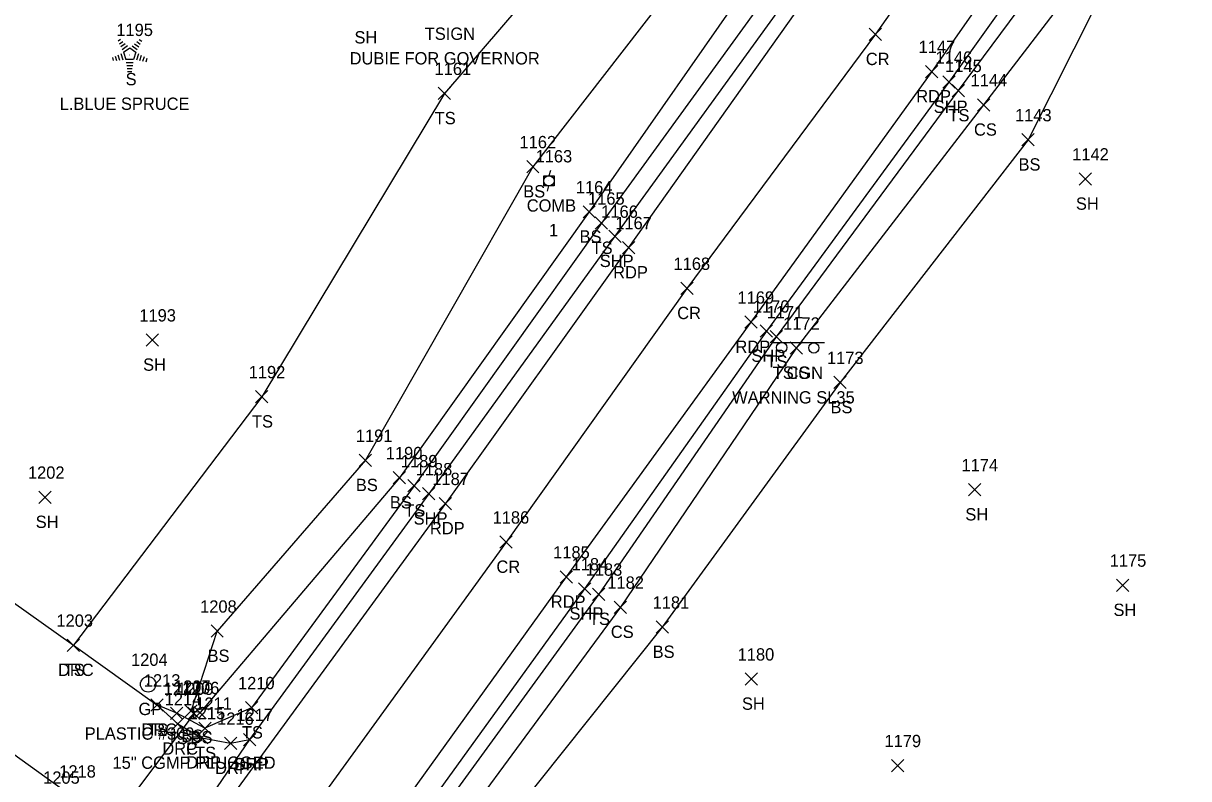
# Model space of a CAD drawing. Extents: x 1520648 to 1523413, y 732854 to 735518.
# Drawn here: x 1522600.4 to 1522789.8, y 734497.2 to 734620 of the extents above; entities that cross this region are included whole.
import ezdxf

# ---------------------------------------------------------------- set-up
doc = ezdxf.new("R2010")
doc.units = 0
for name, color, linetype in [('D_A', 7, 'Continuous'), ('D_C', 7, 'Continuous'), ('D_I', 7, 'Continuous'), ('D_TIC', 7, 'Continuous'), ('DCP', 7, 'Continuous'), ('L_A', 7, 'Continuous'), ('L_C', 7, 'Continuous'), ('L_I', 7, 'Continuous'), ('L_TIC', 7, 'Continuous'), ('LELB', 7, 'Continuous'), ('LTC', 7, 'Continuous'), ('P_A', 7, 'Continuous'), ('P_I', 7, 'Continuous'), ('P_TIC', 7, 'Continuous'), ('PET', 7, 'Continuous'), ('PRC', 7, 'Continuous'), ('PSP', 7, 'Continuous'), ('R_A', 7, 'Continuous'), ('R_C', 7, 'Continuous'), ('R_I', 7, 'Continuous'), ('R_TIC', 7, 'Continuous'), ('RDP', 7, 'Continuous'), ('RGP', 7, 'Continuous'), ('S_A', 7, 'Continuous'), ('S_C', 7, 'Continuous'), ('S_I', 7, 'Continuous'), ('SSGN', 7, 'Continuous'), ('U_A', 7, 'Continuous'), ('U_C', 7, 'Continuous'), ('U_I', 7, 'Continuous'), ('UP', 7, 'Continuous')]:
    doc.layers.add(name, color=color, linetype=linetype)

msp = doc.modelspace()

# ---------------------------------------------------------------- linework, layer by layer
at = {"layer": 'D_TIC'}
for points in [[(1522627.14, 734506.84), (1522629.14, 734508.84)], [(1522629.14, 734506.84), (1522627.14, 734508.84)]]:
    msp.add_lwpolyline(points, dxfattribs=at)
at = {"layer": 'DCP'}
msp.add_lwpolyline([(1522628.14, 734507.84), (1522613.17, 734487.96)], dxfattribs=at)
at = {"layer": 'L_TIC'}
for points in [[(1522667.83, 734607.56), (1522669.83, 734609.56)], [(1522669.83, 734607.56), (1522667.83, 734609.56)], [(1522751.35, 734608.03), (1522753.35, 734610.03)], [(1522753.35, 734608.03), (1522751.35, 734610.03)], [(1522755.48, 734605.7), (1522757.48, 734607.7)], [(1522757.48, 734605.7), (1522755.48, 734607.7)], [(1522762.72, 734600.03), (1522764.72, 734602.03)], [(1522764.72, 734600.03), (1522762.72, 734602.03)], [(1522682.2, 734595.66), (1522684.2, 734597.66)], [(1522684.2, 734595.66), (1522682.2, 734597.66)], [(1522772, 734593.67), (1522774, 734595.67)], [(1522774, 734593.67), (1522772, 734595.67)], [(1522691.36, 734588.33), (1522693.36, 734590.33)], [(1522693.36, 734588.33), (1522691.36, 734590.33)], [(1522693.34, 734586.49), (1522695.34, 734588.49)], [(1522695.34, 734586.49), (1522693.34, 734588.49)], [(1522620.35, 734567.51), (1522622.35, 734569.51)], [(1522622.35, 734567.51), (1522620.35, 734569.51)], [(1522721.77, 734568.04), (1522723.77, 734570.04)], [(1522723.77, 734568.04), (1522721.77, 734570.04)], [(1522725.02, 734566.19), (1522727.02, 734568.19)], [(1522727.02, 734566.19), (1522725.02, 734568.19)], [(1522732.15, 734560.61), (1522734.15, 734562.61)], [(1522734.15, 734560.61), (1522732.15, 734562.61)], [(1522638.13, 734558.29), (1522640.13, 734560.29)], [(1522640.13, 734558.29), (1522638.13, 734560.29)], [(1522654.99, 734547.96), (1522656.99, 734549.96)], [(1522656.99, 734547.96), (1522654.99, 734549.96)], [(1522660.51, 734545.14), (1522662.51, 734547.14)], [(1522662.51, 734545.14), (1522660.51, 734547.14)], [(1522662.89, 734543.83), (1522664.89, 734545.83)], [(1522664.89, 734543.83), (1522662.89, 734545.83)], [(1522754.02, 734543.19), (1522756.02, 734545.19)], [(1522756.02, 734543.19), (1522754.02, 734545.19)], [(1522602.89, 734541.97), (1522604.89, 734543.97)], [(1522604.89, 734541.97), (1522602.89, 734543.97)], [(1522778.1, 734527.67), (1522780.1, 734529.67)], [(1522780.1, 734527.67), (1522778.1, 734529.67)], [(1522692.92, 734526.21), (1522694.92, 734528.21)], [(1522694.92, 734526.21), (1522692.92, 734528.21)], [(1522696.44, 734524.1), (1522698.44, 734526.1)], [(1522698.44, 734524.1), (1522696.44, 734526.1)], [(1522630.88, 734520.21), (1522632.88, 734522.21)], [(1522632.88, 734520.21), (1522630.88, 734522.21)], [(1522630.88, 734520.21), (1522632.88, 734522.21)], [(1522632.88, 734520.21), (1522630.88, 734522.21)], [(1522703.24, 734520.86), (1522705.24, 734522.86)], [(1522705.24, 734520.86), (1522703.24, 734522.86)], [(1522607.52, 734517.92), (1522609.52, 734519.92)], [(1522609.52, 734517.92), (1522607.52, 734519.92)], [(1522717.71, 734512.43), (1522719.71, 734514.43)], [(1522719.71, 734512.43), (1522717.71, 734514.43)], [(1522621.08, 734508.21), (1522623.08, 734510.21)], [(1522623.08, 734508.21), (1522621.08, 734510.21)], [(1522624.31, 734506.86), (1522626.31, 734508.86)], [(1522626.31, 734506.86), (1522624.31, 734508.86)], [(1522626.63, 734507.21), (1522628.63, 734509.21)], [(1522628.63, 734507.21), (1522626.63, 734509.21)], [(1522628.11, 734506.98), (1522630.11, 734508.98)], [(1522630.11, 734506.98), (1522628.11, 734508.98)], [(1522636.49, 734507.77), (1522638.49, 734509.77)], [(1522638.49, 734507.77), (1522636.49, 734509.77)], [(1522628.88, 734504.43), (1522630.88, 734506.43)], [(1522630.88, 734504.43), (1522628.88, 734506.43)], [(1522741.51, 734498.36), (1522743.51, 734500.36)], [(1522743.51, 734498.36), (1522741.51, 734500.36)]]:
    msp.add_lwpolyline(points, dxfattribs=at)
at = {"layer": 'LELB'}
for points in [[(1522855.1, 734830.16), (1522826.24, 734788.65), (1522795.28, 734735.47), (1522774.39, 734704.01), (1522748.32, 734671.46), (1522720.6, 734629.79), (1522692.36, 734589.33), (1522661.51, 734546.14), (1522629.11, 734507.98), (1522627.63, 734508.21), (1522631.88, 734521.21)], [(1522861.38, 734825.29), (1522833.52, 734784.68), (1522798.27, 734733.65), (1522776.55, 734702.76), (1522751.5, 734669.07), (1522723.71, 734627.99), (1522694.34, 734587.49), (1522663.89, 734544.83), (1522637.49, 734508.77), (1522629.88, 734505.43), (1522625.31, 734507.86), (1522622.08, 734509.21)], [(1522751.82, 734797.84), (1522774.11, 734773.6), (1522782.23, 734739.14), (1522764.96, 734707.91), (1522741.94, 734675.96), (1522712.49, 734634.45), (1522683.2, 734596.66), (1522655.99, 734548.96), (1522631.88, 734521.21)], [(1522715.74, 734759.38), (1522736.6, 734748.28), (1522756.98, 734734.14), (1522748.37, 734724.17), (1522727.95, 734685.48), (1522698.99, 734643.64), (1522668.83, 734608.56), (1522639.13, 734559.29), (1522608.52, 734518.92)], [(1522964.59, 734711.8), (1522934.04, 734688.62), (1522903.57, 734670.84), (1522893.31, 734656.71), (1522881.6, 734654.9), (1522856.07, 734664.39), (1522835.94, 734674.96), (1522815.99, 734683.04), (1522809.93, 734682.93), (1522803.99, 734678.79), (1522800.17, 734672.61), (1522781.12, 734647.81), (1522752.35, 734609.03), (1522722.77, 734569.04), (1522693.92, 734527.21), (1522653.61, 734471.8)], [(1522966.98, 734707.81), (1522936.6, 734685.01), (1522907.63, 734664.77), (1522896.44, 734650.45), (1522881.66, 734649.85), (1522854.58, 734659.5), (1522833, 734670.65), (1522815.02, 734680.19), (1522811.05, 734676.42), (1522816.52, 734667.94), (1522809.83, 734658.42), (1522800.06, 734661.2), (1522785.93, 734645.15), (1522763.72, 734601.03), (1522733.15, 734561.61), (1522704.24, 734521.86), (1522660.18, 734466.65)], [(1522785.93, 734645.15), (1522756.48, 734606.7), (1522726.02, 734567.19), (1522697.44, 734525.1), (1522656.53, 734469.54), (1522622.12, 734421.12), (1522590.47, 734378.52), (1522566.34, 734346.2), (1522539.5, 734310.16), (1522511.43, 734266.75), (1522492.81, 734239.83), (1522459.56, 734196.4), (1522434.24, 734163.49), (1522417.99, 734140.69), (1522411.81, 734133.72), (1522406.56, 734130.49), (1522403.25, 734126.38), (1522401.8, 734120.85), (1522386.75, 734098.22)]]:
    msp.add_lwpolyline(points, dxfattribs=at)
at = {"layer": 'LTC'}
for p, q in [((1522615.81, 734617.1), (1522616.16, 734617.36)), ((1522616.02, 734616.63), (1522616.55, 734617.02)), ((1522616.23, 734616.17), (1522616.93, 734616.68)), ((1522616.44, 734615.7), (1522617.32, 734616.34)), ((1522618.47, 734616.64), (1522619.14, 734616.15)), ((1522618.84, 734616.99), (1522619.39, 734616.59)), ((1522619.21, 734617.34), (1522619.63, 734617.04)), ((1522615.3, 734614.6), (1522615.51, 734613.94)), ((1522615.75, 734614.81), (1522616.02, 734613.98)), ((1522616.21, 734615.03), (1522616.54, 734614.01)), ((1522616.66, 734615.25), (1522617.67, 734615.98)), ((1522616.66, 734615.25), (1522617.05, 734614.05)), ((1522617.67, 734615.98), (1522618.67, 734615.26)), ((1522618.09, 734616.3), (1522618.9, 734615.71)), ((1522618.67, 734615.26), (1522618.28, 734614.05)), ((1522619.11, 734614.99), (1522618.77, 734613.95)), ((1522619.55, 734614.74), (1522619.27, 734613.85)), ((1522620, 734614.49), (1522619.76, 734613.76)), ((1522614.84, 734614.38), (1522614.99, 734613.91)), ((1522618.28, 734614.05), (1522617.05, 734614.05)), ((1522618.24, 734613.55), (1522617.1, 734613.55)), ((1522618.16, 734613.05), (1522617.17, 734613.05)), ((1522618.07, 734612.55), (1522617.24, 734612.55)), ((1522620.44, 734614.24), (1522620.26, 734613.66)), ((1522617.99, 734612.05), (1522617.32, 734612.05))]:
    msp.add_line(p, q, dxfattribs=at)
at = {"layer": 'P_TIC'}
for points in [[(1522737.9, 734617.17), (1522739.9, 734619.17)], [(1522739.9, 734617.17), (1522737.9, 734619.17)], [(1522747.04, 734611.12), (1522749.04, 734613.12)], [(1522749.04, 734611.12), (1522747.04, 734613.12)], [(1522749.84, 734609.4), (1522751.84, 734611.4)], [(1522751.84, 734609.4), (1522749.84, 734611.4)], [(1522695.55, 734584.36), (1522697.55, 734586.36)], [(1522697.55, 734584.36), (1522695.55, 734586.36)], [(1522697.77, 734582.51), (1522699.77, 734584.51)], [(1522699.77, 734582.51), (1522697.77, 734584.51)], [(1522707.24, 734575.9), (1522709.24, 734577.9)], [(1522709.24, 734575.9), (1522707.24, 734577.9)], [(1522717.66, 734570.41), (1522719.66, 734572.41)], [(1522719.66, 734570.41), (1522717.66, 734572.41)], [(1522720.18, 734568.96), (1522722.18, 734570.96)], [(1522722.18, 734568.96), (1522720.18, 734570.96)], [(1522665.29, 734542.52), (1522667.29, 734544.52)], [(1522667.29, 734542.52), (1522665.29, 734544.52)], [(1522667.99, 734540.94), (1522669.99, 734542.94)], [(1522669.99, 734540.94), (1522667.99, 734542.94)], [(1522677.84, 734534.68), (1522679.84, 734536.68)], [(1522679.84, 734534.68), (1522677.84, 734536.68)], [(1522687.63, 734529.01), (1522689.63, 734531.01)], [(1522689.63, 734529.01), (1522687.63, 734531.01)], [(1522690.62, 734527.08), (1522692.62, 734529.08)], [(1522692.62, 734527.08), (1522690.62, 734529.08)], [(1522636.15, 734502.6), (1522638.15, 734504.6)], [(1522638.15, 734502.6), (1522636.15, 734504.6)]]:
    msp.add_lwpolyline(points, dxfattribs=at)
at = {"layer": 'PET'}
for points in [[(1522868.59, 734820.36), (1522840.66, 734781.56), (1522808.05, 734736.15), (1522781.8, 734699.35), (1522756.93, 734664.88), (1522728.19, 734624.99), (1522698.77, 734583.51), (1522668.99, 734541.94), (1522630.29, 734488.99), (1522594.44, 734439.3), (1522567.25, 734402.07), (1522538.71, 734362.22), (1522514.31, 734328.64), (1522482.43, 734284.06), (1522464.74, 734260.16), (1522432.63, 734216.53), (1522409.89, 734185.46), (1522384.8, 734151.86)], [(1522887.76, 734807.39), (1522860.85, 734769.52), (1522801.36, 734686.8), (1522776.05, 734652.1), (1522748.04, 734612.12), (1522718.66, 734571.41), (1522688.63, 734530.01), (1522649.15, 734475.23), (1522613.31, 734425.7), (1522584.29, 734385.79), (1522558.85, 734350.63), (1522533.2, 734315.44), (1522501.29, 734271.61), (1522483.1, 734246.38), (1522451.17, 734203.52), (1522426.47, 734169.3), (1522405.75, 734141.77), (1522378.63, 734104.64)]]:
    msp.add_lwpolyline(points, dxfattribs=at)
at = {"layer": 'PRC'}
msp.add_lwpolyline([(1522878.51, 734813.79), (1522851.06, 734774.87), (1522817.97, 734729.86), (1522791.97, 734693.14), (1522766.66, 734657.61), (1522738.9, 734618.17), (1522708.24, 734576.9), (1522678.84, 734535.68), (1522640.14, 734482.21), (1522604.52, 734432.45), (1522576.44, 734394.44), (1522548.3, 734356.14), (1522523.72, 734322.36), (1522491.79, 734277.99), (1522474.03, 734253.33), (1522442.17, 734210.31), (1522417.88, 734177.66), (1522396.73, 734148.57), (1522369.92, 734111.45)], dxfattribs=at)
at = {"layer": 'PSP'}
for points in [[(1522864.28, 734823.23), (1522837.44, 734783.06), (1522805.48, 734737.59), (1522779.45, 734700.71), (1522754.96, 734666.26), (1522726.27, 734626.48), (1522696.55, 734585.36), (1522666.29, 734543.52), (1522637.15, 734503.6), (1522619.94, 734478.45), (1522592.3, 734440.3), (1522565.28, 734403.71), (1522536.3, 734363.73), (1522513.91, 734332.75), (1522468.75, 734270.57), (1522462.45, 734261.84), (1522430.53, 734218.51), (1522407.44, 734186.96), (1522382.7, 734153.4)], [(1522891.61, 734804.38), (1522863.83, 734767.51), (1522842.38, 734738.09), (1522825.83, 734714.72), (1522803.35, 734683.95), (1522778.9, 734649.79), (1522750.84, 734610.4), (1522721.18, 734569.96), (1522691.62, 734528.08), (1522651.91, 734473.19), (1522616.71, 734423.72), (1522586.83, 734383.52), (1522561.92, 734348.87), (1522535.83, 734313.09), (1522504.54, 734270.39), (1522485.78, 734244.5), (1522453.37, 734201.19), (1522428.68, 734167.53), (1522408.2, 734139.28), (1522381.04, 734102.47)]]:
    msp.add_lwpolyline(points, dxfattribs=at)
at = {"layer": 'R_TIC'}
for points in [[(1522607.52, 734517.92), (1522609.52, 734519.92)], [(1522609.52, 734517.92), (1522607.52, 734519.92)], [(1522621.08, 734508.21), (1522623.08, 734510.21)], [(1522623.08, 734508.21), (1522621.08, 734510.21)], [(1522624.48, 734505.14), (1522626.48, 734507.14)], [(1522626.48, 734505.14), (1522624.48, 734507.14)], [(1522624.48, 734505.14), (1522626.48, 734507.14)], [(1522626.48, 734505.14), (1522624.48, 734507.14)], [(1522628.37, 734502.89), (1522630.37, 734504.89)], [(1522630.37, 734502.89), (1522628.37, 734504.89)], [(1522636.15, 734502.6), (1522638.15, 734504.6)], [(1522638.15, 734502.6), (1522636.15, 734504.6)], [(1522633.07, 734501.99), (1522635.07, 734503.99)], [(1522635.07, 734501.99), (1522633.07, 734503.99)]]:
    msp.add_lwpolyline(points, dxfattribs=at)
at = {"layer": 'RDP'}
for points in [[(1522568.98, 734547.78), (1522593.47, 734529.59), (1522608.52, 734518.92), (1522622.08, 734509.21), (1522625.48, 734506.14)], [(1522557.87, 734531.39), (1522583.51, 734512.2), (1522608.33, 734494.42), (1522613.93, 734490.74)], [(1522625.48, 734506.14), (1522629.37, 734503.89), (1522634.07, 734502.99), (1522637.15, 734503.6)]]:
    msp.add_lwpolyline(points, dxfattribs=at)
at = {"layer": 'RGP'}
msp.add_line((1522620.66, 734512.57), (1522620.66, 734512.57), dxfattribs=at)
for radius in [1.25, 0.0833]:
    msp.add_circle((1522620.66, 734512.57), radius, dxfattribs=at)
at = {"layer": 'SSGN'}
for p, q in [((1522722, 734568.11), (1522730.6, 734568.11)), ((1522726.02, 734567.21), (1522726.02, 734567.21))]:
    msp.add_line(p, q, dxfattribs=at)
for centre in [(1522723.66, 734567.28), (1522728.88, 734567.21)]:
    msp.add_circle(centre, 0.833, dxfattribs=at)
at = {"layer": 'UP'}
for p, q in [((1522686.07, 734596.03), (1522685.82, 734595.19)), ((1522684.99, 734593.53), (1522684.99, 734595.19)), ((1522684.99, 734595.19), (1522686.66, 734595.19)), ((1522685.82, 734594.36), (1522685.82, 734594.36)), ((1522686.66, 734595.19), (1522686.66, 734593.53)), ((1522686.66, 734593.53), (1522684.99, 734593.53)), ((1522685.57, 734592.69), (1522685.82, 734593.53))]:
    msp.add_line(p, q, dxfattribs=at)
msp.add_circle((1522685.82, 734594.36), 0.833, dxfattribs=at)

# ---------------------------------------------------------------- texts
at = {"layer": 'D_A'}
msp.add_text('P', height=2, dxfattribs=at).set_placement((1522627.52, 734502.84))
at = {"layer": 'D_C'}
msp.add_text('15" CGMP PLUGGED', height=2, dxfattribs=at).set_placement((1522614.87, 734498.84))
at = {"layer": 'D_I'}
msp.add_text('1209', height=2, dxfattribs=at).set_placement((1522625.36, 734510.84))
at = {"layer": 'L_A'}
for s, p in [('SH', (1522654.2, 734616.68)), ('S', (1522617, 734609.89)), ('TS', (1522667.24, 734603.56)), ('TS', (1522750.76, 734604.03)), ('CS', (1522754.92, 734601.7)), ('BS', (1522762.16, 734596.03)), ('BS', (1522681.64, 734591.66)), ('SH', (1522771.49, 734589.67)), ('BS', (1522690.8, 734584.33)), ('TS', (1522692.75, 734582.49)), ('SH', (1522619.84, 734563.51)), ('TS', (1522721.18, 734564.04)), ('CS', (1522724.46, 734562.19)), ('BS', (1522731.59, 734556.61)), ('TS', (1522637.54, 734554.29)), ('BS', (1522654.43, 734543.96)), ('BS', (1522659.96, 734541.14)), ('TS', (1522662.3, 734539.83)), ('SH', (1522753.51, 734539.19)), ('SH', (1522602.38, 734537.97)), ('SH', (1522777.59, 734523.67)), ('TS', (1522692.32, 734522.21)), ('CS', (1522695.88, 734520.1)), ('BS', (1522630.32, 734516.21)), ('BS', (1522630.32, 734516.21)), ('BS', (1522702.68, 734516.86)), ('TS', (1522606.93, 734513.92)), ('SH', (1522717.2, 734508.43)), ('TS', (1522620.49, 734504.21)), ('TS', (1522623.72, 734502.86)), ('BS', (1522626.07, 734503.21)), ('BS', (1522627.55, 734502.98)), ('TS', (1522635.9, 734503.77)), ('TS', (1522628.29, 734500.43))]:
    msp.add_text(s, height=2, dxfattribs=at).set_placement(p)
at = {"layer": 'L_C'}
msp.add_text('L.BLUE SPRUCE', height=2, dxfattribs=at).set_placement((1522606.28, 734605.89))
at = {"layer": 'L_I'}
for s, p in [('1195', (1522615.49, 734617.89)), ('1161', (1522667.22, 734611.56)), ('1145', (1522750.23, 734612.03)), ('1144', (1522754.36, 734609.7)), ('1143', (1522761.59, 734604.03)), ('1162', (1522681.03, 734599.66)), ('1142', (1522770.88, 734597.67)), ('1164', (1522690.19, 734592.33)), ('1165', (1522692.17, 734590.49)), ('1193', (1522619.23, 734571.51)), ('1171', (1522721.21, 734572.04)), ('1172', (1522723.89, 734570.19)), ('1173', (1522731.02, 734564.61)), ('1192', (1522637.01, 734562.29)), ('1191', (1522654.43, 734551.96)), ('1190', (1522659.3, 734549.14)), ('1189', (1522661.75, 734547.83)), ('1174', (1522752.89, 734547.19)), ('1202', (1522601.12, 734545.97)), ('1175', (1522776.98, 734531.67)), ('1183', (1522691.79, 734530.21)), ('1182', (1522695.31, 734528.1)), ('1208', (1522629.11, 734524.21)), ('1208', (1522629.11, 734524.21)), ('1181', (1522702.68, 734524.86)), ('1203', (1522605.75, 734521.92)), ('1180', (1522716.5, 734516.43)), ('1213', (1522619.96, 734512.21)), ('1212', (1522623.18, 734510.86)), ('1207', (1522624.86, 734511.21)), ('1206', (1522626.28, 734510.98)), ('1210', (1522635.27, 734511.77)), ('1211', (1522628.32, 734508.43)), ('1179', (1522740.37, 734502.36)), ('1218', (1522606.21, 734497.42))]:
    msp.add_text(s, height=2, dxfattribs=at).set_placement(p)
at = {"layer": 'LTC'}
msp.add_text('.', height=1.04, rotation=270, dxfattribs=at).set_placement((1522617.56, 734615))
at = {"layer": 'P_A'}
for s, p in [('CR', (1522737.33, 734613.17)), ('RDP', (1522745.53, 734607.12)), ('SHP', (1522748.37, 734605.4)), ('SHP', (1522694.08, 734580.36)), ('RDP', (1522696.26, 734578.51)), ('CR', (1522706.67, 734571.9)), ('RDP', (1522716.14, 734566.41)), ('SHP', (1522718.72, 734564.96)), ('SHP', (1522663.82, 734538.52)), ('RDP', (1522666.47, 734536.94)), ('CR', (1522677.28, 734530.68)), ('RDP', (1522686.12, 734525.01)), ('SHP', (1522689.16, 734523.08)), ('SHP', (1522634.68, 734498.6))]:
    msp.add_text(s, height=2, dxfattribs=at).set_placement(p)
at = {"layer": 'P_I'}
for s, p in [('1147', (1522745.91, 734615.12)), ('1146', (1522748.66, 734613.4)), ('1166', (1522694.32, 734588.36)), ('1167', (1522696.6, 734586.51)), ('1168', (1522706.07, 734579.9)), ('1169', (1522716.47, 734574.41)), ('1170', (1522718.97, 734572.96)), ('1188', (1522664.16, 734546.52)), ('1187', (1522666.86, 734544.94)), ('1186', (1522676.66, 734538.68)), ('1185', (1522686.5, 734533.01)), ('1184', (1522689.5, 734531.08)), ('1217', (1522635.02, 734506.6))]:
    msp.add_text(s, height=2, dxfattribs=at).set_placement(p)
at = {"layer": 'R_A'}
for s, p in [('DRC', (1522606.01, 734513.92)), ('GP', (1522619.09, 734507.57)), ('DRC', (1522619.57, 734504.21)), ('DRC', (1522622.97, 734501.14)), ('DRP', (1522622.97, 734501.14)), ('DRP', (1522626.86, 734498.89)), ('DRP', (1522631.55, 734497.99)), ('DRP', (1522634.63, 734498.6))]:
    msp.add_text(s, height=2, dxfattribs=at).set_placement(p)
at = {"layer": 'R_C'}
msp.add_text('PLASTIC #309', height=2, dxfattribs=at).set_placement((1522610.35, 734503.57))
at = {"layer": 'R_I'}
for s, p in [('1203', (1522605.75, 734521.92)), ('1204', (1522617.88, 734515.57)), ('1213', (1522619.96, 734512.21)), ('1214', (1522623.35, 734509.14)), ('1214', (1522623.35, 734509.14)), ('1215', (1522627.24, 734506.89)), ('1217', (1522635.02, 734506.6)), ('1216', (1522631.88, 734505.99)), ('1218', (1522606.21, 734497.42)), ('1205', (1522603.59, 734496.42))]:
    msp.add_text(s, height=2, dxfattribs=at).set_placement(p)
at = {"layer": 'S_A'}
for p in [(1522665.63, 734617.27), (1522722.2, 734562.19)]:
    msp.add_text('TSIGN', height=2, dxfattribs=at).set_placement(p)
at = {"layer": 'S_C'}
for s, p in [('DUBIE FOR GOVERNOR', (1522653.42, 734613.27)), ('WARNING SL35', (1522715.61, 734558.19))]:
    msp.add_text(s, height=2, dxfattribs=at).set_placement(p)
at = {"layer": 'S_I'}
msp.add_text('1172', height=2, dxfattribs=at).set_placement((1522723.89, 734570.19))
at = {"layer": 'U_A'}
msp.add_text('COMB', height=2, dxfattribs=at).set_placement((1522682.21, 734589.36))
at = {"layer": 'U_C'}
msp.add_text('1', height=2, dxfattribs=at).set_placement((1522685.82, 734585.36))
at = {"layer": 'U_I'}
msp.add_text('1163', height=2, dxfattribs=at).set_placement((1522683.65, 734597.36))

doc.saveas('drawing.dxf')
